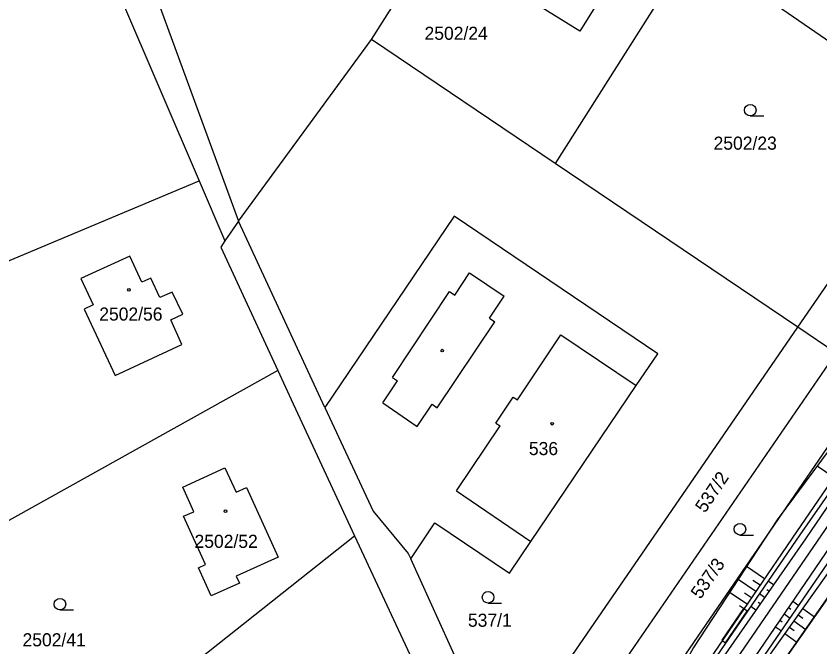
# Model space of a CAD drawing. Extents: x -558358 to -557517, y -1073786 to -1073189.
# Drawn here: x -558303.9 to -558199.4, y -1073504 to -1073422.1 of the extents above; entities that cross this region are included whole.
import ezdxf

# ---------------------------------------------------------------- set-up
doc = ezdxf.new("R2010")
doc.units = 0
for name, color, linetype in [('Hranice parcel', 7, 'Continuous'), ('Kolej', 7, 'Continuous'), ('Lomové body_krizky', 7, 'Continuous'), ('Návěst ostatní', 7, 'Continuous'), ('Parcelní čísla', 7, 'Continuous'), ('Plot - zábradlí', 7, 'Continuous'), ('Přejezd - štěrkové lože', 7, 'Continuous'), ('Sonda - šrafa - vrstevnice', 7, 'Continuous'), ('Svazek obcí údolí Desné', 7, 'Continuous'), ('Vnitřní kresba', 7, 'Continuous'), ('Značky budov', 7, 'Continuous'), ('Značky kultur', 7, 'Continuous')]:
    doc.layers.add(name, color=color, linetype=linetype)

msp = doc.modelspace()

# ---------------------------------------------------------------- linework, layer by layer
at = {"layer": 'Hranice parcel'}
for p, q in [((-558257.7, -1073425.14), (-558239.77, -1073396.82)), ((-558288.18, -1073412.71), (-558274.97, -1073448.74)), ((-558216.02, -1073413.17), (-558233.8, -1073441.26)), ((-558291.74, -1073416.28), (-558280.07, -1073443.5)), ((-558274.97, -1073448.74), (-558257.7, -1073425.14)), ((-558233.8, -1073441.26), (-558257.7, -1073425.14)), ((-558202.26, -1073462.53), (-558233.8, -1073441.26)), ((-558351.92, -1073473.58), (-558280.07, -1073443.5)), ((-558280.07, -1073443.5), (-558276.72, -1073451.31)), ((-558274.97, -1073448.74), (-558276.72, -1073451.31)), ((-558263.73, -1073472.95), (-558274.97, -1073448.74)), ((-558197.28, -1073465.89), (-558202.26, -1073462.53)), ((-558269.87, -1073468.15), (-558339.52, -1073506.95)), ((-558325.69, -1073541.72), (-558259.89, -1073489.61)), ((-558246.29, -1073506.44), (-558252.58, -1073492.61))]:
    msp.add_line(p, q, dxfattribs=at)
for points in [[(-558232.07, -1073410.99), (-558225.13, -1073415.34), (-558230.62, -1073424.08), (-558237.55, -1073419.73), (-558232.07, -1073410.99)], [(-558202.26, -1073462.53), (-558188.73, -1073442.87), (-558187.31, -1073436.01), (-558191.04, -1073430.36), (-558216.02, -1073413.17)], [(-558252.58, -1073492.61), (-558249.44, -1073487.92), (-558239.75, -1073494.46), (-558236.97, -1073490.34), (-558223.28, -1073470.09), (-558220.49, -1073465.96), (-558246.94, -1073448.09), (-558263.73, -1073472.95)], [(-558276.72, -1073451.31), (-558277.28, -1073452.14), (-558269.87, -1073468.15)], [(-558287.54, -1073456.66), (-558289.07, -1073453.28), (-558295.45, -1073456.18), (-558293.85, -1073459.61), (-558295.04, -1073460.19), (-558290.99, -1073468.78), (-558282.34, -1073464.77), (-558283.75, -1073461.57), (-558282.21, -1073460.84), (-558283.59, -1073457.95), (-558285.18, -1073458.67), (-558286.36, -1073456.15), (-558287.54, -1073456.66)], [(-558246.29, -1073506.44), (-558241.75, -1073510.46), (-558234.37, -1073508.88), (-558231.59, -1073505.15), (-558202.26, -1073462.53)], [(-558235.03, -1073522.1), (-558231.61, -1073515.78), (-558197.28, -1073465.89)], [(-558269.87, -1073468.15), (-558267.87, -1073472.49), (-558259.89, -1073489.61)], [(-558263.73, -1073472.95), (-558257.48, -1073486.4), (-558252.9, -1073491.92), (-558252.58, -1073492.61)], [(-558280.17, -1073493.77), (-558279.26, -1073493.36), (-558282.12, -1073487.08), (-558280.77, -1073486.48), (-558282.2, -1073483.29), (-558276.72, -1073480.79), (-558275.28, -1073483.95), (-558273.92, -1073483.36), (-558269.81, -1073492.38), (-558275.26, -1073494.86), (-558274.85, -1073495.76), (-558278.51, -1073497.42), (-558280.17, -1073493.77)], [(-558259.89, -1073489.61), (-558244.04, -1073523.6), (-558239.03, -1073535.96)]]:
    msp.add_lwpolyline(points, dxfattribs=at)
at = {"layer": 'Kolej'}
msp.add_lwpolyline([(-558222.5, -1073523.52), (-558211.35, -1073507.26), (-558189.16, -1073474.89), (-558177.86, -1073458.42), (-558166.63, -1073442.09)], dxfattribs=at)
at = {"layer": 'Lomové body_krizky'}
for points in [[(-558160.27, -1073422.61), (-558170.92, -1073439.28), (-558182.07, -1073455.63), (-558193.45, -1073472.04), (-558204.95, -1073487.53), (-558215.83, -1073504.11), (-558218.74, -1073509.41), (-558221.47, -1073511.54)], [(-558158.61, -1073423.97), (-558169.15, -1073440.42), (-558180.26, -1073456.88), (-558191.27, -1073472.78), (-558202.46, -1073489.11), (-558213.8, -1073505.71), (-558218.06, -1073510.9), (-558220.02, -1073511.36), (-558220.66, -1073512.06)], [(-558152.7, -1073428.17), (-558163.49, -1073444.26), (-558174.92, -1073460.4), (-558186.51, -1073476.58), (-558197.24, -1073492.86), (-558208.77, -1073509.05), (-558219.85, -1073525.27), (-558227.1, -1073535.75), (-558230.39, -1073540.52), (-558231, -1073543.03)]]:
    msp.add_lwpolyline(points, dxfattribs=at)
at = {"layer": 'Návěst ostatní'}
for p, q in [((-558209.34, -1073499.06), (-558212.17, -1073503.19)), ((-558211.68, -1073503.52), (-558208.85, -1073499.4)), ((-558209.34, -1073499.06), (-558209.84, -1073498.72)), ((-558208.85, -1073499.4), (-558209.34, -1073499.06)), ((-558212.17, -1073503.19), (-558211.68, -1073503.52))]:
    msp.add_line(p, q, dxfattribs=at)
at = {"layer": 'Plot - zábradlí'}
msp.add_lwpolyline([(-558226.6, -1073552.39), (-558229.62, -1073542.12), (-558228.84, -1073541.34), (-558220.94, -1073529.81), (-558210.66, -1073515.21), (-558195.56, -1073493.62), (-558184.31, -1073477.57), (-558177.73, -1073468.27), (-558161.67, -1073445.55), (-558150.68, -1073429.95)], dxfattribs=at)
at = {"layer": 'Přejezd - štěrkové lože'}
for p, q in [((-558205.45, -1073495.98), (-558206.12, -1073495.51)), ((-558206.6, -1073497.62), (-558207.25, -1073497.16)), ((-558206.03, -1073496.8), (-558206.29, -1073496.61)), ((-558207.17, -1073498.44), (-558207.43, -1073498.26)), ((-558202.92, -1073498.11), (-558202.14, -1073498.65)), ((-558207.74, -1073499.26), (-558208.38, -1073498.81)), ((-558203.49, -1073498.94), (-558203.17, -1073499.15)), ((-558204.05, -1073499.76), (-558203.27, -1073500.3)), ((-558205.18, -1073501.42), (-558204.4, -1073501.95)), ((-558204.61, -1073500.59), (-558204.3, -1073500.8))]:
    msp.add_line(p, q, dxfattribs=at)
for points in [[(-558233.12, -1073536.27), (-558231.44, -1073532.59), (-558224.31, -1073522.11), (-558213.32, -1073506.02), (-558201.98, -1073489.48), (-558190.68, -1073473.3), (-558179.76, -1073457.16), (-558168.65, -1073440.76), (-558157.79, -1073424.72)], [(-558157.06, -1073425.16), (-558168.03, -1073441.18), (-558179.14, -1073457.55), (-558190.46, -1073474.12), (-558201.29, -1073490), (-558212.69, -1073506.36), (-558223.92, -1073522.5), (-558230.65, -1073533.02), (-558233.12, -1073536.27)], [(-558154.33, -1073427.06), (-558164.84, -1073443.28), (-558176.23, -1073459.59), (-558187.79, -1073475.9), (-558198.67, -1073491.89), (-558209.91, -1073508.33), (-558221.19, -1073524.36), (-558228.27, -1073535), (-558231.51, -1073539.54)], [(-558231.51, -1073539.54), (-558230.18, -1073538.97), (-558227.65, -1073535.49), (-558220.31, -1073524.95), (-558209.15, -1073508.87), (-558197.9, -1073492.46), (-558187.04, -1073476.34), (-558175.63, -1073459.98), (-558164.25, -1073443.72), (-558153.52, -1073427.77)]]:
    msp.add_lwpolyline(points, dxfattribs=at)
at = {"layer": 'Sonda - šrafa - vrstevnice'}
for p, q in [((-558197.61, -1073482.04), (-558199.78, -1073480.56)), ((-558206.62, -1073495.2), (-558208.94, -1073493.61)), ((-558207.75, -1073496.85), (-558210.04, -1073495.28)), ((-558207.19, -1073496.02), (-558208.11, -1073495.4)), ((-558208.88, -1073498.5), (-558211.14, -1073496.96)), ((-558208.32, -1073497.68), (-558209.22, -1073497.05)), ((-558201.64, -1073499.04), (-558200.11, -1073500.13)), ((-558202.22, -1073499.86), (-558201.61, -1073500.29)), ((-558203.38, -1073501.49), (-558202.76, -1073501.93)), ((-558202.8, -1073500.67), (-558201.26, -1073501.77)), ((-558203.96, -1073502.3), (-558202.41, -1073503.41))]:
    msp.add_line(p, q, dxfattribs=at)
at = {"layer": 'Svazek obcí údolí Desné'}
for p, q in [((-558177.75, -1073468.29), (-558220.99, -1073529.81)), ((-558192.36, -1073469.21), (-558234.96, -1073531.36))]:
    msp.add_line(p, q, dxfattribs=at)
at = {"layer": 'Vnitřní kresba'}
for p, q in [((-558246.86, -1073458.35), (-558244.94, -1073455.47)), ((-558244.94, -1073455.47), (-558240.43, -1073458.48)), ((-558254.96, -1073469.03), (-558247.53, -1073457.9)), ((-558247.53, -1073457.9), (-558246.86, -1073458.35)), ((-558242.35, -1073461.35), (-558240.43, -1073458.48)), ((-558249.13, -1073472.99), (-558241.66, -1073461.81)), ((-558242.35, -1073461.35), (-558241.66, -1073461.81)), ((-558238.73, -1073471.97), (-558233.06, -1073463.5)), ((-558233.06, -1073463.5), (-558223.28, -1073470.09)), ((-558254.96, -1073469.03), (-558254.3, -1073469.47)), ((-558256.21, -1073472.34), (-558254.3, -1073469.47)), ((-558241.52, -1073474.97), (-558239.27, -1073471.61)), ((-558239.27, -1073471.61), (-558238.73, -1073471.97)), ((-558256.21, -1073472.34), (-558251.73, -1073475.41)), ((-558251.73, -1073475.41), (-558249.81, -1073472.53)), ((-558249.81, -1073472.53), (-558249.13, -1073472.99)), ((-558246.65, -1073483.79), (-558240.98, -1073475.33)), ((-558241.52, -1073474.97), (-558240.98, -1073475.33)), ((-558246.65, -1073483.79), (-558236.97, -1073490.34))]:
    msp.add_line(p, q, dxfattribs=at)
at = {"layer": 'Značky budov'}
for centre in [(-558289.2, -1073457.65), (-558248.48, -1073465.56), (-558234.2, -1073475.05), (-558276.67, -1073486.42)]:
    msp.add_circle(centre, 0.175, dxfattribs=at)
at = {"layer": 'Značky kultur'}
for p, q in [((-558208.46, -1073435.07), (-558206.71, -1073435.07)), ((-558209.8, -1073489.51), (-558208.05, -1073489.51)), ((-558242.54, -1073498.35), (-558240.79, -1073498.35)), ((-558298.17, -1073499.24), (-558296.42, -1073499.24))]:
    msp.add_line(p, q, dxfattribs=at)
for centre in [(-558208.46, -1073434.32), (-558209.8, -1073488.76), (-558242.54, -1073497.6), (-558298.17, -1073498.49)]:
    msp.add_circle(centre, 0.75, dxfattribs=at)

# ---------------------------------------------------------------- texts
at = {"layer": 'Parcelní čísla'}
for s, p in [('2502/24', (-558250.79, -1073425.19)), ('2502/23', (-558213.23, -1073439.46)), ('2502/56', (-558293.06, -1073461.66)), ('536', (-558237.23, -1073479.13)), ('2502/52', (-558280.68, -1073491.18)), ('537/1', (-558245.15, -1073501.43)), ('2502/41', (-558303.03, -1073503.97))]:
    msp.add_text(s, height=1.7, dxfattribs=at).set_placement(p)
for s, rotation, p in [('537/2', 56, (-558214.34, -1073486.74)), ('537/3', 55, (-558214.94, -1073497.94))]:
    msp.add_text(s, height=1.7, rotation=rotation, dxfattribs=at).set_placement(p)

doc.saveas('drawing.dxf')
